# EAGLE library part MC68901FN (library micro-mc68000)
68xxx PROCESSOR
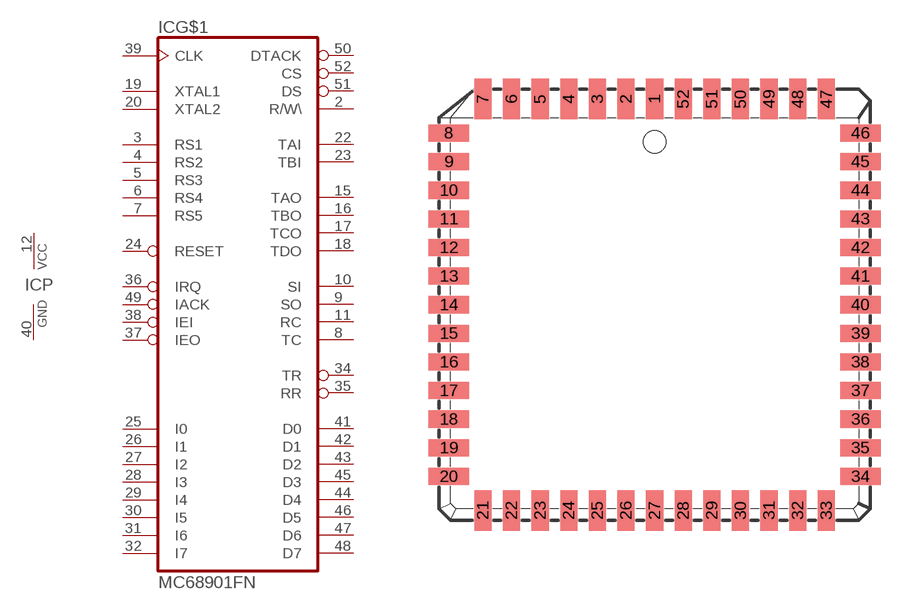
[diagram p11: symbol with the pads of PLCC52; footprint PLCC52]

Designator prefix IC; gates G$1=68901 P=PWRN

## MC68901FN  [PLCC52]
2  G$1:R/W\  in
3  G$1:RS1  in
4  G$1:RS2  in
5  G$1:RS3  in
6  G$1:RS4  in
7  G$1:RS5  in
8  G$1:TC  in
9  G$1:SO  out
10  G$1:SI  in
11  G$1:RC  in
12  P:VCC  pwr
15  G$1:TAO  out
16  G$1:TBO  out
17  G$1:TCO  out
18  G$1:TDO  out
19  G$1:XTAL1  in
20  G$1:XTAL2  in
22  G$1:TAI  in
23  G$1:TBI  in
24  G$1:RESET  in
25  G$1:I0
26  G$1:I1
27  G$1:I2
28  G$1:I3
29  G$1:I4
30  G$1:I5
31  G$1:I6
32  G$1:I7
34  G$1:TR  out
35  G$1:RR  out
36  G$1:IRQ  out
37  G$1:IEO  out
38  G$1:IEI  in
39  G$1:CLK  in
40  P:GND  pwr
41  G$1:D0
42  G$1:D1
43  G$1:D2
44  G$1:D4
45  G$1:D3
46  G$1:D5
47  G$1:D6
48  G$1:D7
49  G$1:IACK  in
50  G$1:DTACK  out
51  G$1:DS  in
52  G$1:CS  in

## Footprint PLCC52 (pad centres in mm)
PLASTIC LEADED CHIP CARRIER square
smd 0.76 x 1.8: 1 0,9.13; 2 -1.27,9.13; 3 -2.54,9.13; 4 -3.81,9.13; 5 -5.08,9.13; 6 -6.35,9.13; 7 -7.62,9.13; 21 -7.62,-9.13; 22 -6.35,-9.13; 23 -5.08,-9.13; 24 -3.81,-9.13; 25 -2.54,-9.13; 26 -1.27,-9.13; 27 0,-9.13; 28 1.27,-9.13; 29 2.54,-9.13; 30 3.81,-9.13; 31 5.08,-9.13; 32 6.35,-9.13; 33 7.62,-9.13; 47 7.62,9.13; 48 6.35,9.13; 49 5.08,9.13; 50 3.81,9.13; 51 2.54,9.13; 52 1.27,9.13
smd 1.8 x 0.76: 8 -9.13,7.62; 9 -9.13,6.35; 10 -9.13,5.08; 11 -9.13,3.81; 12 -9.13,2.54; 13 -9.13,1.27; 14 -9.13,0; 15 -9.13,-1.27; 16 -9.13,-2.54; 17 -9.13,-3.81; 18 -9.13,-5.08; 19 -9.13,-6.35; 20 -9.13,-7.62; 34 9.13,-7.62; 35 9.13,-6.35; 36 9.13,-5.08; 37 9.13,-3.81; 38 9.13,-2.54; 39 9.13,-1.27; 40 9.13,0; 41 9.13,1.27; 42 9.13,2.54; 43 9.13,3.81; 44 9.13,5.08; 45 9.13,6.35; 46 9.13,7.62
